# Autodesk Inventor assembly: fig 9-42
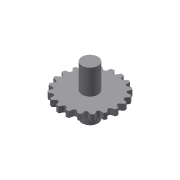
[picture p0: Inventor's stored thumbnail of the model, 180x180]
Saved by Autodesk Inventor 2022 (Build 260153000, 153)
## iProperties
Created: 2013-07
Part Number: fig 9-42
Document SubType Name: Assembly
Designer: CADCIM
Author: CADCIM
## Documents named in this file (3)
- D:\PROJECTS_2021\Resources\Part Files\c09_Inv_2022_prt\fig 9-43.iam
- D:\PROJECTS_2021\Resources\Part Files\c09_Inv_2022_prt\13.ipt
- D:\PROJECTS_2021\Resources\Part Files\c09_Inv_2022_prt\14.ipt
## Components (2 placed, 2 different names)
1. 13:1 — Rotational:1
2. 14:1 — Rotational:1
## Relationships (1: RevoluteJoint 1)
- Rotational:1 [RevoluteJoint]: 13:1 ↔ 14:1
